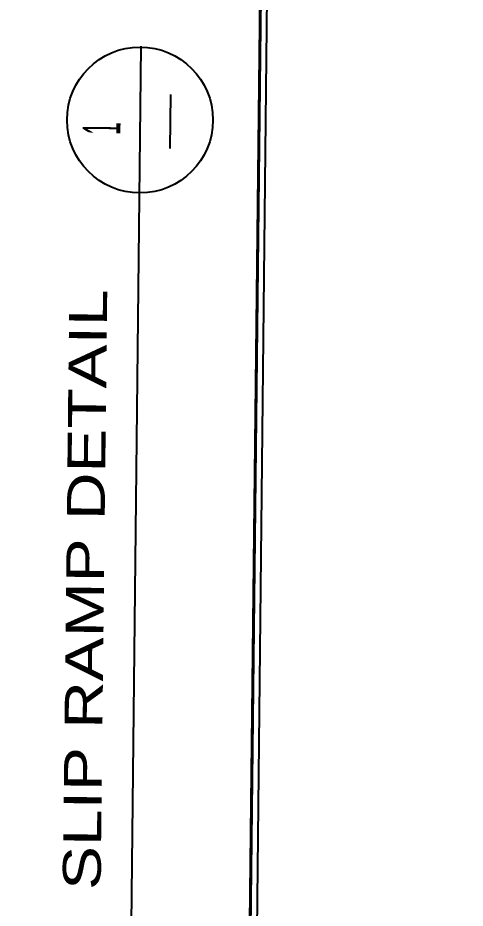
# Model space of a CAD drawing. Extents: x 2356576 to 2377878, y 6966390 to 6990634.
# Drawn here: x 2366792 to 2367164, y 6974475 to 6975215 of the extents above; entities that cross this region are included whole.
import ezdxf
from ezdxf.enums import TextEntityAlignment as Align

# ---------------------------------------------------------------- set-up
doc = ezdxf.new("R2010")
doc.units = 0
doc.header["$LTSCALE"] = 7.1
doc.layers.add('19', color=7, linetype='Continuous', lineweight=13)
doc.layers.add('8', color=7, linetype='Continuous', lineweight=13)

msp = doc.modelspace()

# ---------------------------------------------------------------- linework, layer by layer
at = {"layer": '19', "lineweight": 40}
for p, q in [((2366886.132, 6974461.668), (2366894.232, 6975191.256)), ((2366918.492, 6975106.184), (2366918.992, 6975151.18))]:
    msp.add_line(p, q, dxfattribs=at)
msp.add_lwpolyline([(2363758.773, 6990629.355), (2367158.576, 6990592.767), (2366922.891, 6968646.236), (2363523.088, 6968682.826)], close=True, dxfattribs=at)
at = {"layer": '19', "lineweight": 25}
msp.add_lwpolyline([(2366974.866, 6973617.03), (2367000.838, 6975955.59), (2366117.376, 6975965.402), (2366091.406, 6973626.842)], close=True, dxfattribs=at)
at = {"layer": '19', "lineweight": 40}
msp.add_circle((2366893.308, 6975129.943), 60.65, dxfattribs=at)
at = {"layer": '8', "lineweight": 40}
for p, q in [((2366886.132, 6974461.668), (2366894.232, 6975191.256)), ((2366918.492, 6975106.184), (2366918.992, 6975151.18))]:
    msp.add_line(p, q, dxfattribs=at)
for points in [[(2363753.827, 6990634.409), (2367163.63, 6990597.713), (2366927.837, 6968641.182), (2363518.034, 6968677.88)], [(2363758.773, 6990629.355), (2367158.576, 6990592.767), (2366922.891, 6968646.236), (2363523.088, 6968682.826)]]:
    msp.add_lwpolyline(points, close=True, dxfattribs=at)
at = {"layer": '8', "lineweight": 25}
msp.add_lwpolyline([(2366974.866, 6973617.03), (2367000.838, 6975955.59), (2366117.376, 6975965.402), (2366091.406, 6973626.842)], close=True, dxfattribs=at)
at = {"layer": '8', "lineweight": 40}
msp.add_circle((2366893.308, 6975129.943), 60.65, dxfattribs=at)

# ---------------------------------------------------------------- texts
at = {"layer": '19'}
for s, width, p in [('1', 0.45, (2366877.058, 6975122.729)), ('SLIP RAMP DETAIL', 1.3, (2366863.31, 6974739.476))]:
    msp.add_text(s, height=31.5, rotation=89.364, dxfattribs=dict(at, width=width)).set_placement(p, align=Align.CENTER)
at = {"layer": '8'}
for s, width, p in [('1', 0.45, (2366877.058, 6975122.729)), ('SLIP RAMP DETAIL', 1.3, (2366863.31, 6974739.476))]:
    msp.add_text(s, height=31.5, rotation=89.364, dxfattribs=dict(at, width=width)).set_placement(p, align=Align.CENTER)

doc.saveas('drawing.dxf')
